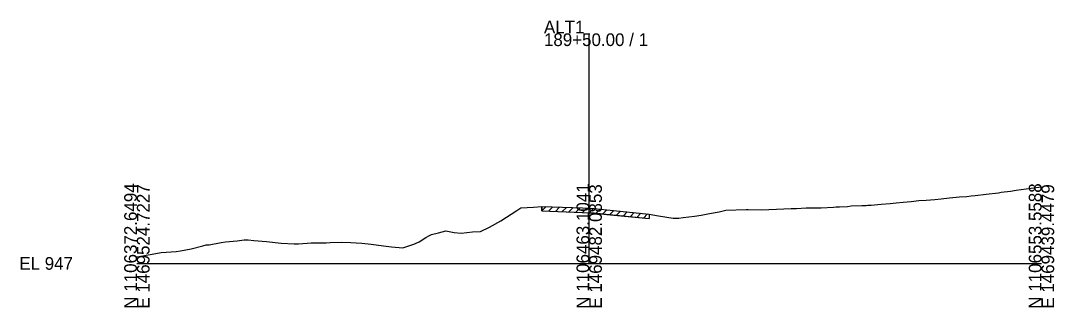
# Model space of a CAD drawing. Extents: x -26 to 2203, y -10 to 19568.
# Drawn here: x 1974.3 to 2202.8, y 11490.3 to 11553.6 of the extents above; entities that cross this region are included whole.
import ezdxf

# ---------------------------------------------------------------- set-up
doc = ezdxf.new("R2010")
doc.units = 0
for name, color, linetype in [('RD_GPK_XS_Cell', 7, 'Continuous'), ('RD_XS_ExGround', 7, 'Continuous'), ('RD_XS_ExPaveRet', 7, 'Continuous')]:
    doc.layers.add(name, color=color, linetype=linetype)

msp = doc.modelspace()

# ---------------------------------------------------------------- linework, layer by layer
at = {"layer": 'RD_GPK_XS_Cell'}
for p, q in [((2100, 11500), (2100, 11550.81)), ((2000, 11500), (2100, 11500)), ((2100, 11500), (2200, 11500))]:
    msp.add_line(p, q, dxfattribs=at)
at = {"layer": 'RD_XS_ExGround'}
msp.add_lwpolyline([(2000, 11501.46), (2000.52, 11501.55), (2002.05, 11501.84), (2003.4, 11502.06), (2005.36, 11502.41), (2007.56, 11502.54), (2008.68, 11502.64), (2009.68, 11502.81), (2012, 11503.25), (2014.59, 11503.86), (2015.31, 11504.07), (2015.95, 11504.14), (2018.63, 11504.61), (2019.59, 11504.75), (2022.14, 11504.97), (2023.73, 11505.19), (2024.63, 11505.2), (2025.86, 11505.06), (2028.67, 11504.86), (2031.9, 11504.47), (2034.77, 11504.35), (2035.37, 11504.33), (2035.7, 11504.35), (2037.62, 11504.46), (2038.53, 11504.54), (2041.05, 11504.56), (2041.84, 11504.58), (2042.74, 11504.62), (2045.16, 11504.71), (2047.32, 11504.59), (2048.48, 11504.56), (2049.77, 11504.45), (2051.79, 11504.24), (2053.4, 11504.03), (2055.11, 11503.78), (2056.26, 11503.69), (2058.8, 11503.46), (2061.22, 11504.28), (2062.42, 11504.79), (2063.85, 11505.69), (2064.67, 11506.2), (2065.13, 11506.41), (2066.66, 11506.75), (2068.31, 11507.16), (2070.14, 11506.85), (2071.69, 11506.68), (2074.17, 11506.95), (2075.95, 11507.08), (2077.98, 11508.02), (2080.45, 11509.37), (2083.97, 11511.66), (2084.87, 11512.24), (2087.69, 11512.46), (2089.53, 11512.6), (2098.5, 11512.25), (2100, 11512.18), (2101.1, 11512.13), (2103.88, 11511.84), (2113.28, 11510.89), (2115.35, 11510.5), (2118.56, 11509.99), (2119.34, 11509.99), (2119.84, 11510.03), (2120.78, 11510.16), (2123.28, 11510.4), (2124.76, 11510.66), (2125.53, 11510.79), (2126.61, 11511), (2128.74, 11511.42), (2130.23, 11511.76), (2134.71, 11511.94), (2135.16, 11511.93), (2138.03, 11511.87), (2141.43, 11511.98), (2144.66, 11512.1), (2145.82, 11512.14), (2147.98, 11512.25), (2148.28, 11512.25), (2151.29, 11512.24), (2153.98, 11512.43), (2154.61, 11512.48), (2155.32, 11512.51), (2157.09, 11512.6), (2157.93, 11512.7), (2160.25, 11512.77), (2161.24, 11512.81), (2161.6, 11512.85), (2162.35, 11512.89), (2163.85, 11513.03), (2164.56, 11513.07), (2166.53, 11513.26), (2167.87, 11513.39), (2169.39, 11513.5), (2171.19, 11513.66), (2172.87, 11513.87), (2174.51, 11513.97), (2176.42, 11514.15), (2177.82, 11514.29), (2179.63, 11514.49), (2181.14, 11514.63), (2181.88, 11514.74), (2183.46, 11514.81), (2184.46, 11514.9), (2185.35, 11514.99), (2187.77, 11515.33), (2190.5, 11515.62), (2191.09, 11515.7), (2193.15, 11515.97), (2194.41, 11516.15), (2197.72, 11516.63), (2200, 11516.94)], dxfattribs=at)
at = {"layer": 'RD_XS_ExPaveRet'}
for p, q in [((2089.53, 11512.6), (2089.53, 11511.6)), ((2089.53, 11511.62), (2089.53, 11512.59)), ((2089.53, 11511.62), (2090.47, 11512.56)), ((2089.53, 11511.62), (2098.63, 11511.26)), ((2089.53, 11511.59), (2098.44, 11511.24)), ((2091.03, 11511.56), (2091.97, 11512.5)), ((2092.53, 11511.5), (2093.47, 11512.44)), ((2094.03, 11511.44), (2094.97, 11512.38)), ((2095.53, 11511.38), (2096.47, 11512.32)), ((2097.03, 11511.32), (2097.97, 11512.26)), ((2098.44, 11511.24), (2100, 11511.17)), ((2098.53, 11511.24), (2099.49, 11512.19)), ((2098.63, 11511.26), (2100, 11511.2)), ((2100, 11511.2), (2101.09, 11511.15)), ((2100.03, 11511.19), (2100.96, 11512.13)), ((2101.53, 11511.08), (2102.43, 11511.99)), ((2103.03, 11510.93), (2103.93, 11511.83)), ((2104.53, 11510.78), (2105.43, 11511.68)), ((2106.03, 11510.63), (2106.93, 11511.53)), ((2107.53, 11510.47), (2108.43, 11511.38)), ((2109.03, 11510.32), (2109.93, 11511.22)), ((2101.09, 11511.15), (2103.72, 11510.88)), ((2101.1, 11511.13), (2103.88, 11510.84)), ((2103.72, 11510.88), (2113.27, 11509.91)), ((2103.88, 11510.84), (2113.28, 11509.89)), ((2110.53, 11510.17), (2111.43, 11511.07)), ((2112.03, 11510.02), (2112.93, 11510.92)), ((2113.27, 11509.91), (2113.28, 11509.91)), ((2113.28, 11510.91), (2113.28, 11509.91)), ((2113.28, 11510.89), (2113.28, 11509.89))]:
    msp.add_line(p, q, dxfattribs=at)

# ---------------------------------------------------------------- texts
at = {"layer": 'RD_GPK_XS_Cell'}
for s, p in [('ALT1', (2090, 11550.81)), ('189+50.00 / 1', (2090, 11548.01)), ('EL 947', (1974, 11498.6))]:
    msp.add_text(s, height=2.8, dxfattribs=at).set_placement(p)
for s, p in [('N 1106372.6494', (2000, 11490)), ('E 1469524.7227', (2002.8, 11490)), ('N 1106463.1041', (2100, 11490)), ('E 1469482.0853', (2102.8, 11490)), ('N 1106553.5588', (2200, 11490)), ('E 1469439.4479', (2202.8, 11490))]:
    msp.add_text(s, height=2.8, rotation=90, dxfattribs=at).set_placement(p)

doc.saveas('drawing.dxf')
